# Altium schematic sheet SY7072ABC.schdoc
size 127 x 101 mm
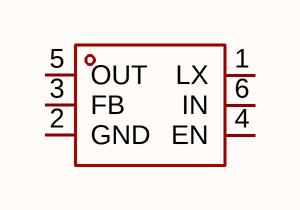
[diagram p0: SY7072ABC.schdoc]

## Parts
U?  sy7072abc  [SOT-23-6_L2.9-W1.6-P0.95-LS2.9-BL]  (value not drawn)

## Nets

Not connected (* = marked no-connect by the designer): U? 1(LX) 2(GND) 3(FB) 4(EN) 5(OUT) 6(IN)

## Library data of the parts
U? = sy7072abc: 功能类型:升压型;工作电压:1.8V~5.5V;输出电压:1.8V~5.5V;输出电流:2A;输出类型:可调;; Manufacturer: Silergy(矽力杰); AddInBom: yes; ModelId: 7835d1ec76e347009cd4512957858e4e; ModelTransform: 114.173,114.173,0,0,0,0,0,0,0; Function: 升压型; Output Current: 2A; Frequency - Switching: 1MHz; Synchronous Rectifier: 是; Number of Outputs: 1; Topology: 升压式; Quiescent Current: 5uA; Switch tube (built-in/external): 内置; Output Type: 可调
